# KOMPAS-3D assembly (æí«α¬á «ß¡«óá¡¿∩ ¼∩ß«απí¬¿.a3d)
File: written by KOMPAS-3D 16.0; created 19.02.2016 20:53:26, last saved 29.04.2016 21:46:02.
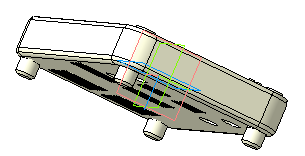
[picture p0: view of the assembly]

Referenced files in T:\оитод\основные детали\: основание корпуса.m3d, Амортизатор (4 шт).m3d, подушечка (8 шт).m3d
Referenced files in T:\оитод\80%\: Шайба.m3d
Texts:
  (-) Амортизатор (1)
  (-) Амортизатор (2)
  (-) Амортизатор (3)
  (-) Амортизатор (4)
  (-) подушечка (1)
  (-) подушечка (2)
  (-) подушечка (3)
  (-) подушечка (4)
  (-) подушечка (5)
  (-) подушечка (6)
  (-) подушечка (7)
  (-) подушечка (8)
  (-) Шайба (1)
  (-) Шайба (2)
  (-) Шайба (3)
  (-) Шайба (4)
